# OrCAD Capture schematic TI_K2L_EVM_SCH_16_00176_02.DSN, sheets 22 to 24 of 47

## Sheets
22 PAGE25 : K2L_GPS AND USIM: size C; title: USIM, SOC UART 1.8v switching, 1.8v/3.3v GPIO INT, SOC UART, GPS
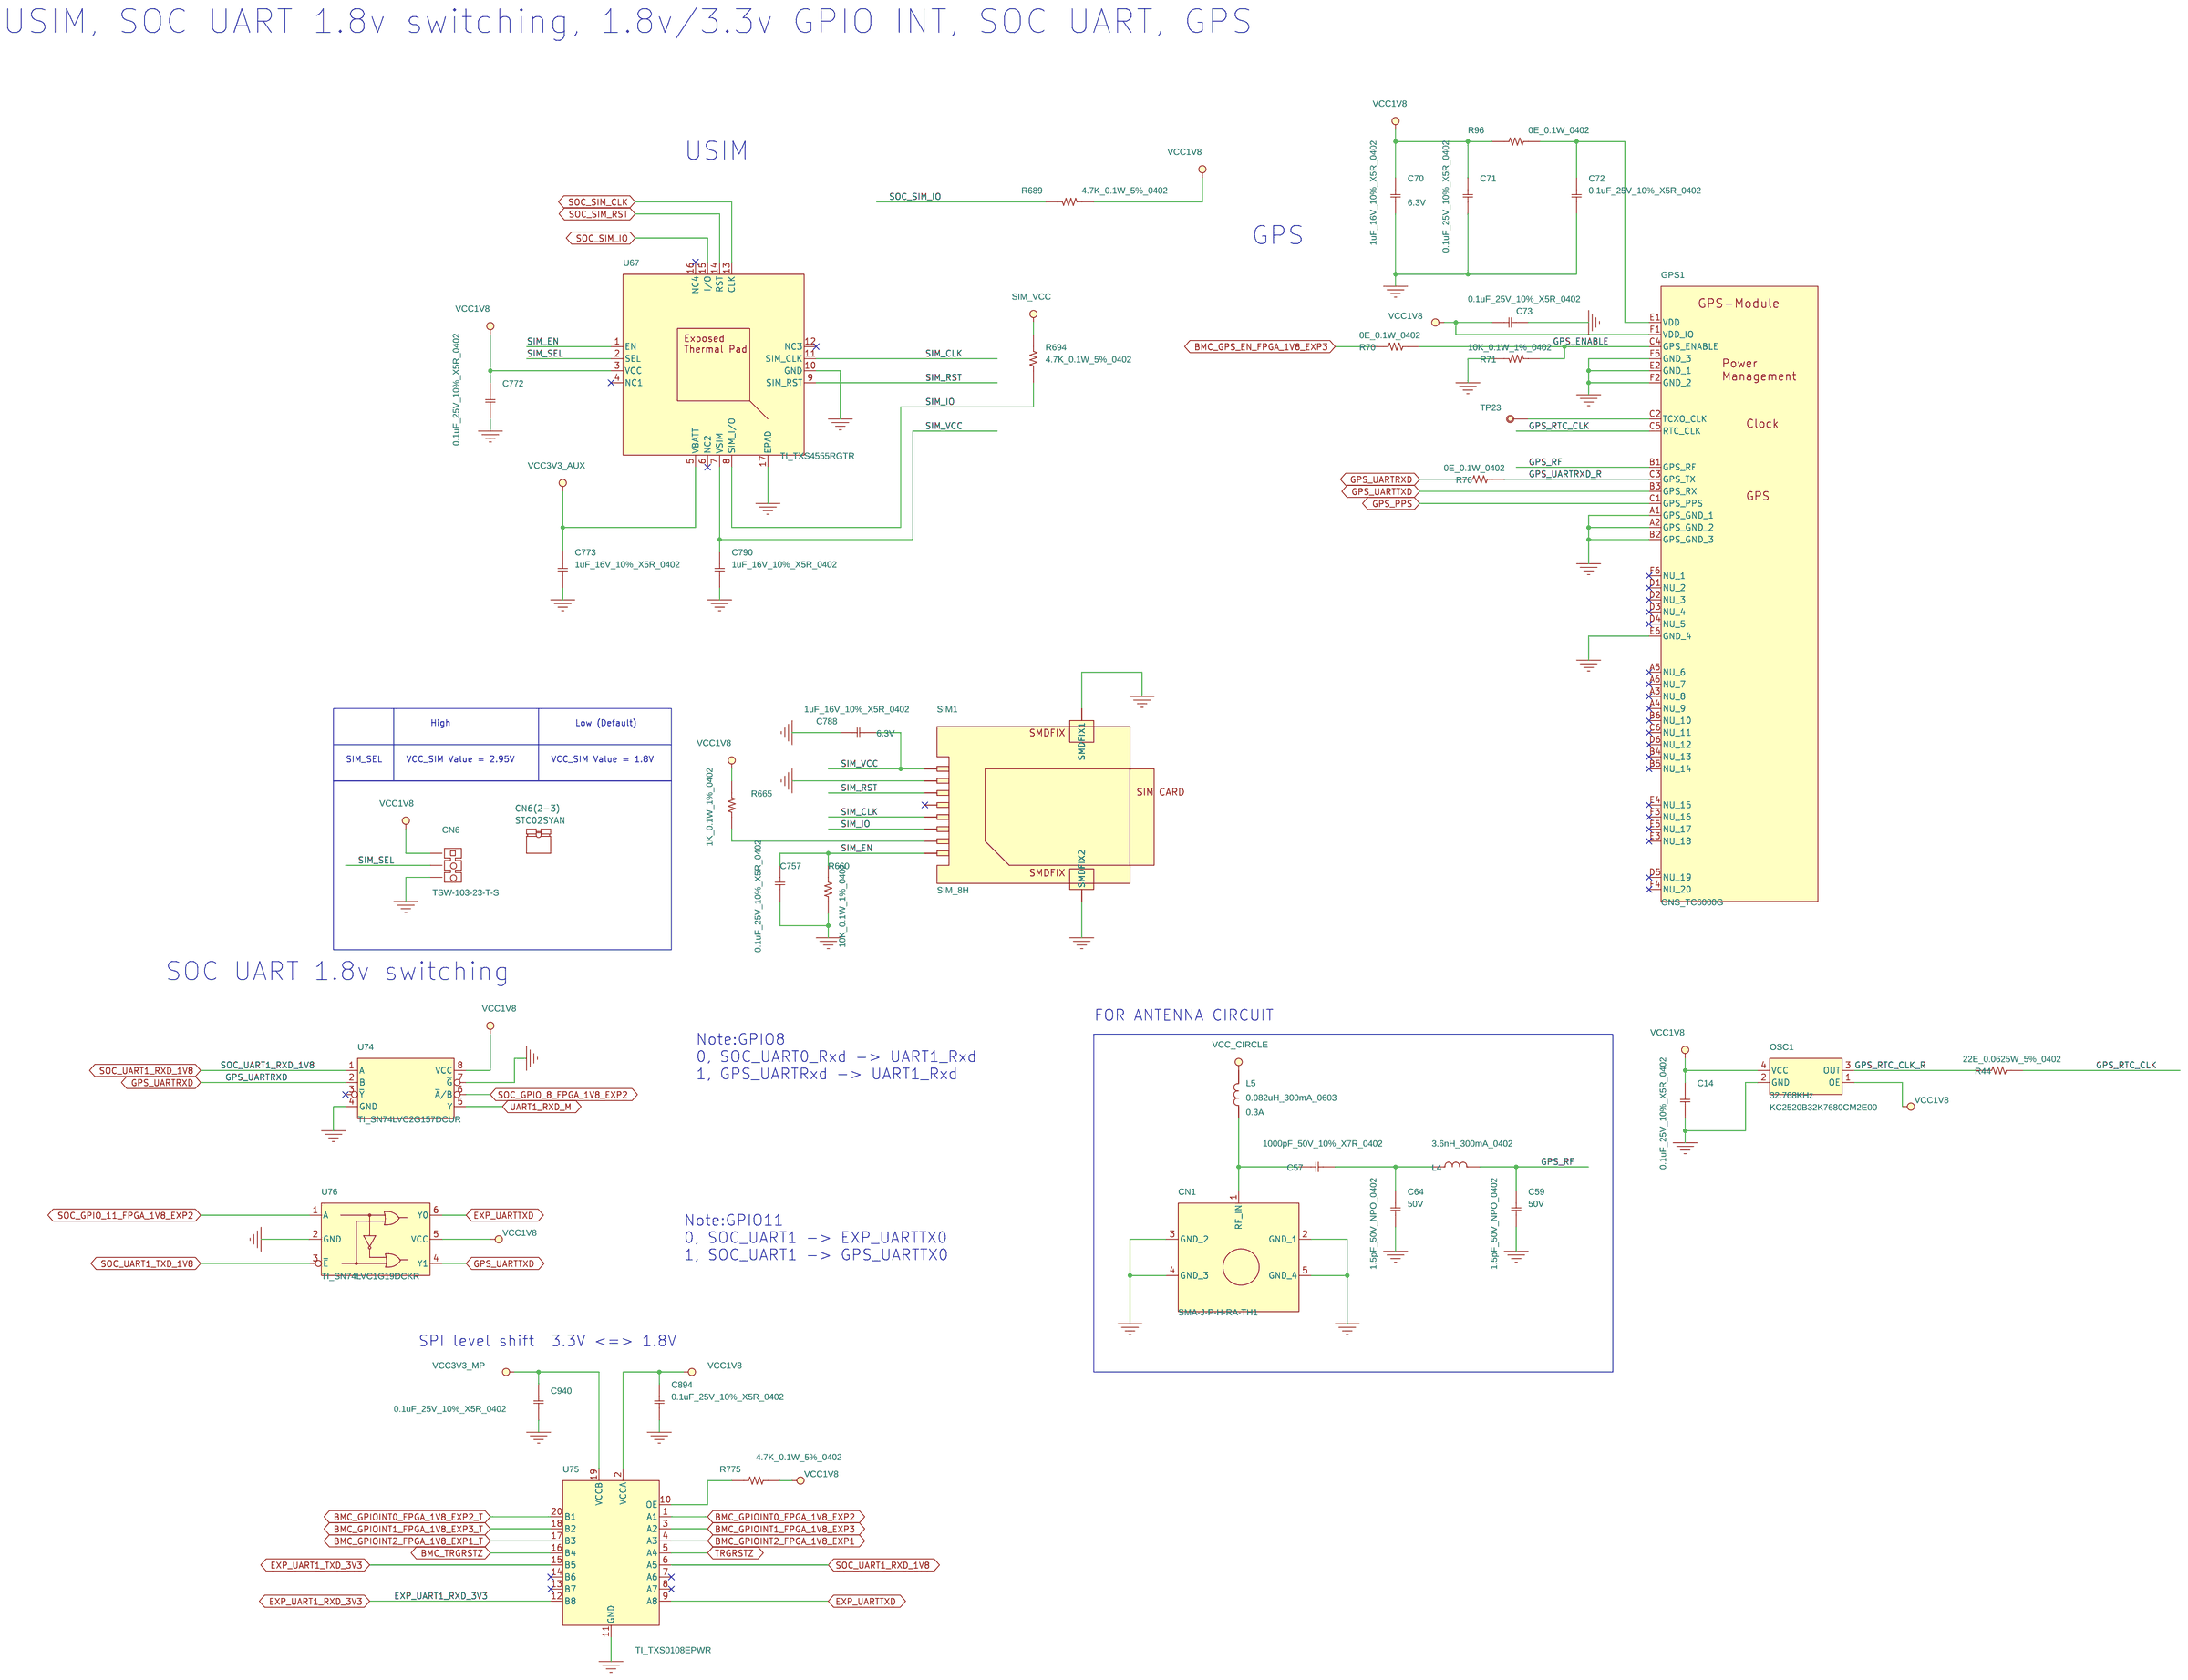
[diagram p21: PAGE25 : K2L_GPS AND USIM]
23 PAGE06 : POWER SEQUENCE_C: title: POWER SEQUENCE
24 PAGE40 : K2L_XDS200_POWER: size C; title: XDS200 Power
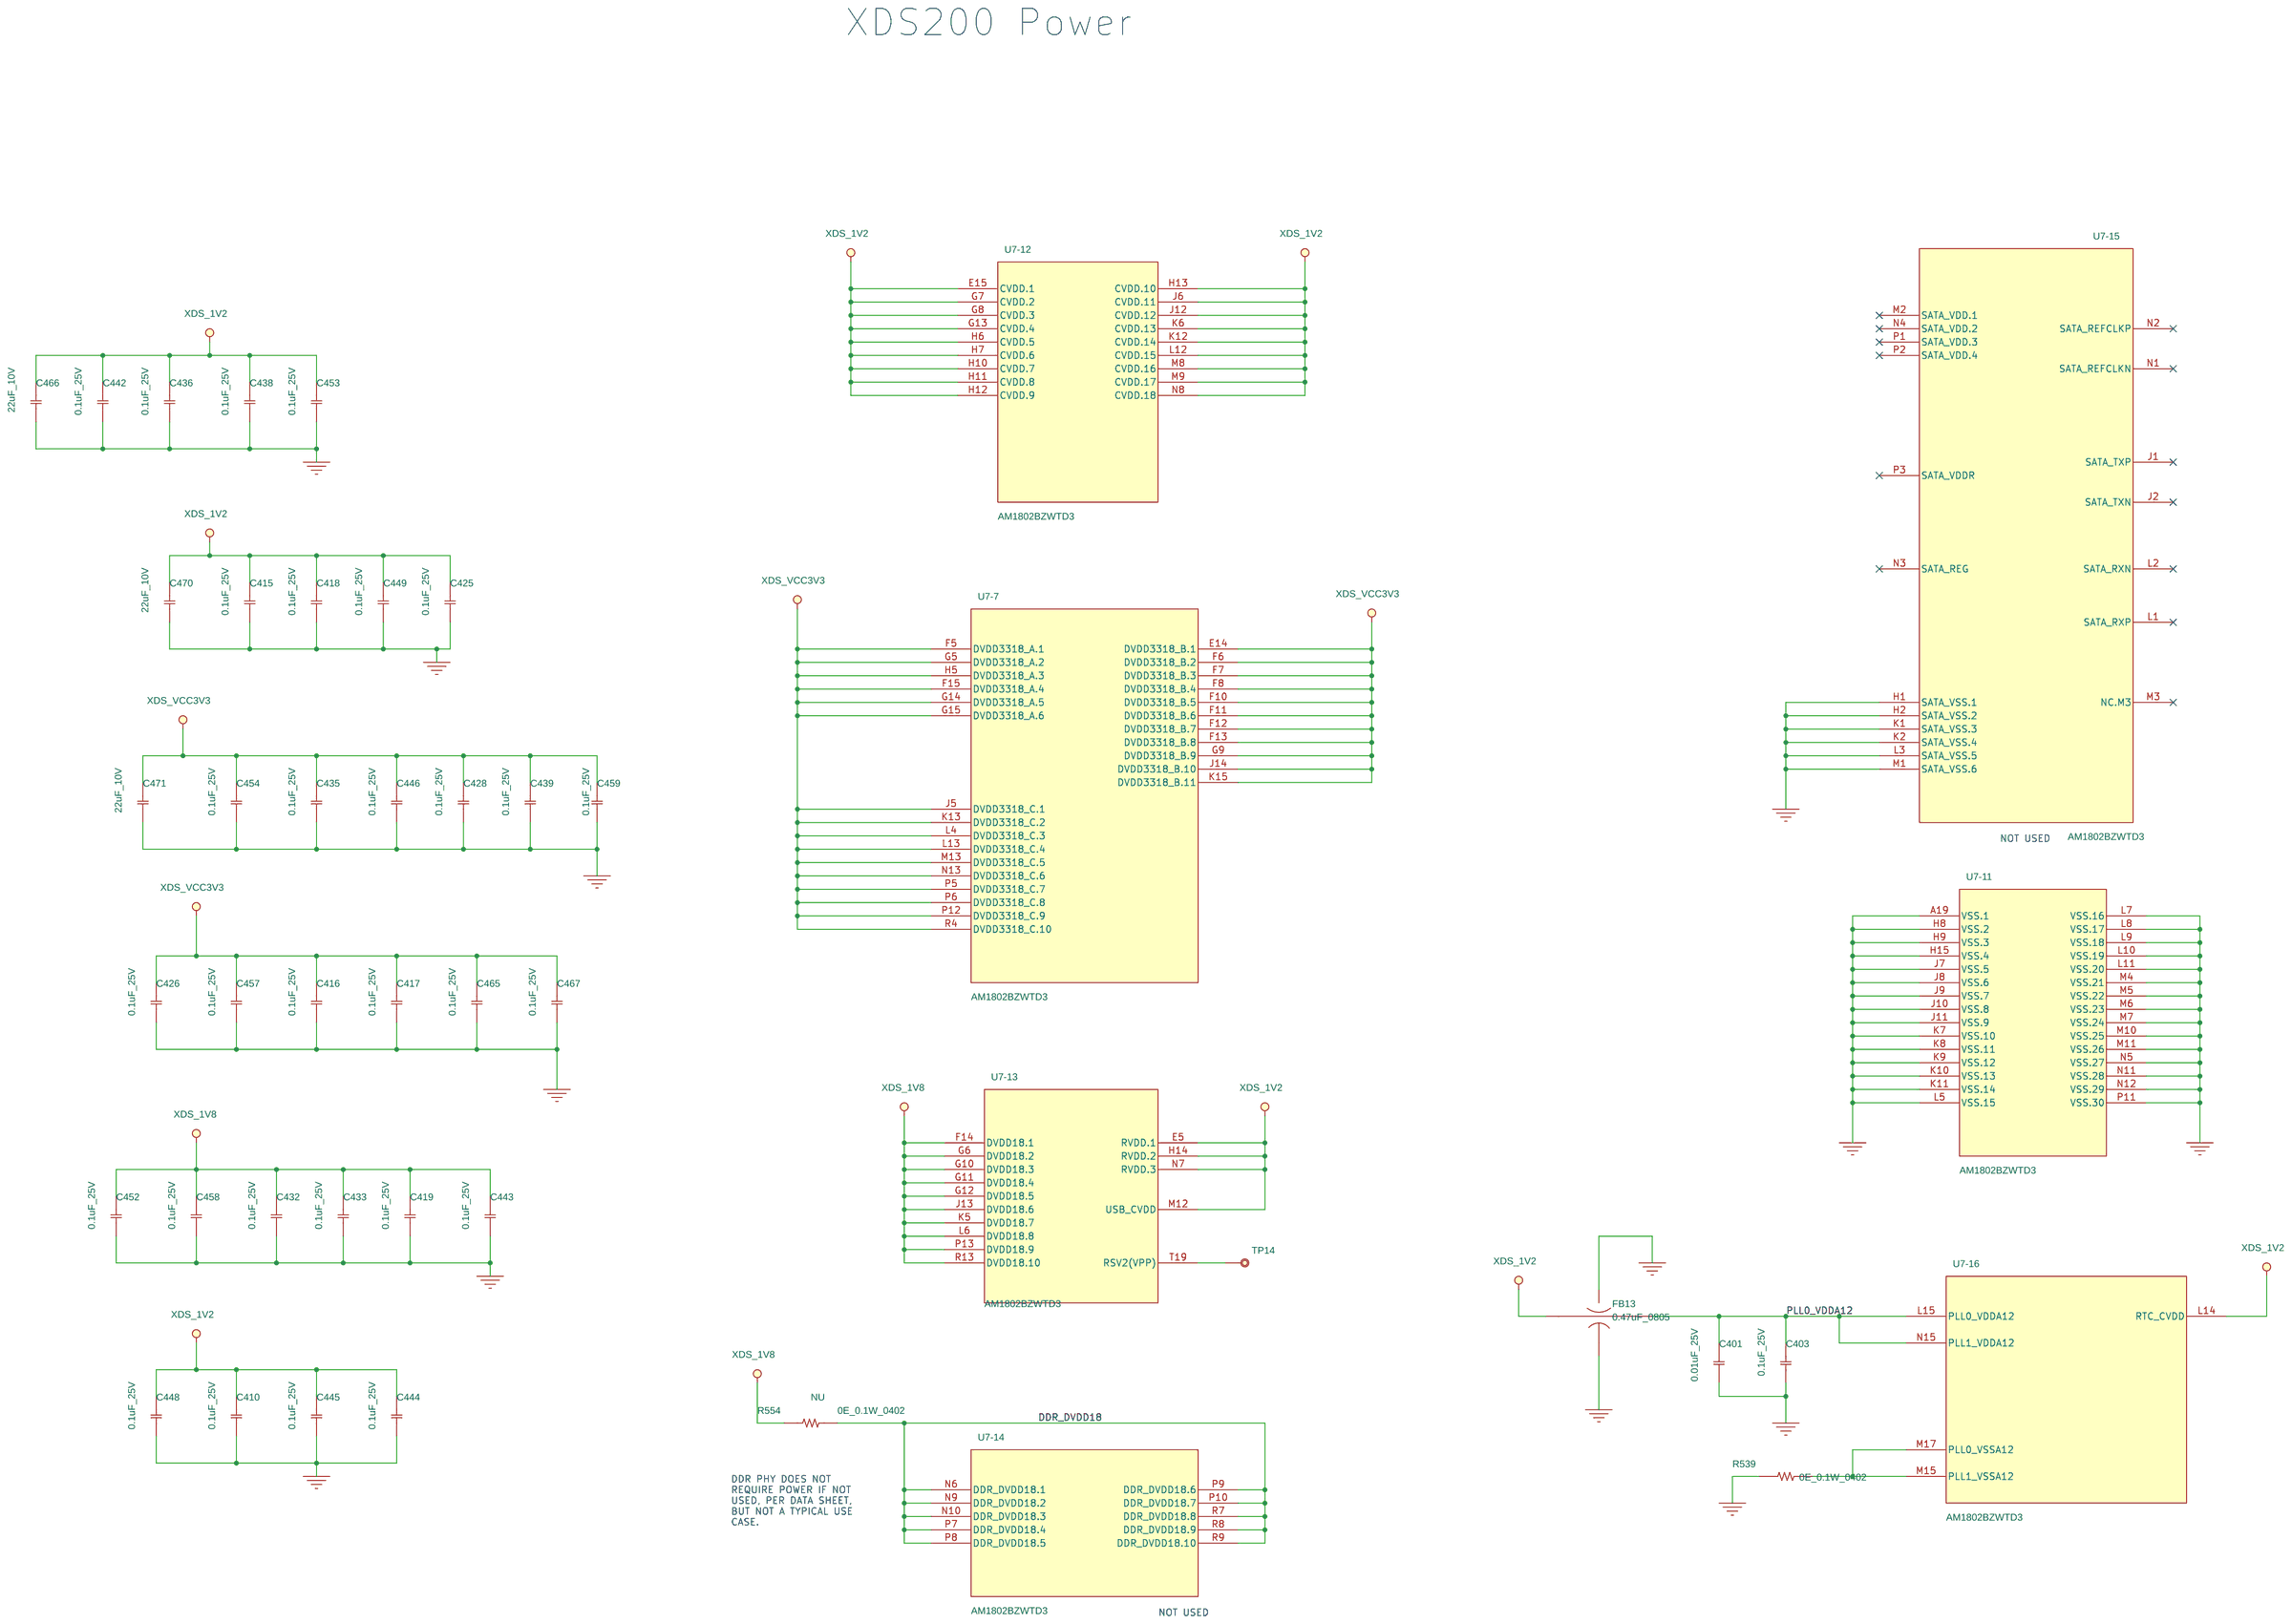
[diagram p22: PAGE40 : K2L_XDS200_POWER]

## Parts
sheet PAGE25 : K2L_GPS AND USIM
C14  0.1uF_25V_10%_X5R_0402  [C0402]
C57  1000pF_50V_10%_X7R_0402  [C0402]
C59  1.5pF_50V_NPO_0402  [C0402]
C64  1.5pF_50V_NPO_0402  [C0402]
C70  1uF_16V_10%_X5R_0402  [C0402]
C71  0.1uF_25V_10%_X5R_0402  [C0402]
C72  0.1uF_25V_10%_X5R_0402  [C0402]
C73  0.1uF_25V_10%_X5R_0402  [C0402]
C757  0.1uF_25V_10%_X5R_0402  [C0402]
C772  0.1uF_25V_10%_X5R_0402  [C0402]
C773  1uF_16V_10%_X5R_0402  [C0402]
C788  1uF_16V_10%_X5R_0402  [C0402]
C790  1uF_16V_10%_X5R_0402  [C0402]
C894  0.1uF_25V_10%_X5R_0402  [C0402]
C940  0.1uF_25V_10%_X5R_0402  [C0402]
CN1  SMA-J-P-H-RA-TH1  [SAMSMA-J-P-H-RA-TH1]
CN6  TSW-103-23-T-S  [BERG_1X3]
CN6(2-3)  STC02SYAN  [NA]
GPS1  GNS_TC6000G  [BGA_36P_60_394x366]
L4  3.6nH_300mA_0402  [L0402]
L5  0.082uH_300mA_0603  [INDC1608X95N]
OSC1  32.768KHz  [OSCCC200X250X70-4N]
R44  22E_0.0625W_5%_0402  [R0402]
R70  0E_0.1W_0402  [R0402]
R71  10K_0.1W_1%_0402  [R0402]
R76  0E_0.1W_0402  [R0402]
R96  0E_0.1W_0402  [R0402]
R660  10K_0.1W_1%_0402  [R0402]
R665  1K_0.1W_1%_0402  [R0402]
R689  4.7K_0.1W_5%_0402  [R0402]
R694  4.7K_0.1W_5%_0402  [R0402]
R775  4.7K_0.1W_5%_0402  [R0402]
SIM1  SIM_8H  [SIM_8P_FMS006Z-2001-1]
TP23  TP  [TP-S40]
U67  TI_TXS4555RGTR  [QFN_16P_20_118x118_TP59]
U74  TI_SN74LVC2G157DCUR  [SOIC_8P_20_79X122]
U75  TI_TXS0108EPWR  [SOIC_20P_26_256x252]
U76  TI_SN74LVC1G19DCKR  [SC-70_6P]
sheet PAGE39 : K2L_XDS200_3
U7  AM1802BZWTD3  [BGA80P_16X16_361]  (sections -1,-10,-11,-12,-13,-14,-15,-16,-2,-3,-4,-5,-6,-7,-8,-9)
sheet PAGE40 : K2L_XDS200_POWER
C401  0.01uF_25V  [C0402]
C403  0.1uF_25V  [C0402]
C410  0.1uF_25V  [C0402]
C415  0.1uF_25V  [C0402]
C416  0.1uF_25V  [C0402]
C417  0.1uF_25V  [C0402]
C418  0.1uF_25V  [C0402]
C419  0.1uF_25V  [C0402]
C425  0.1uF_25V  [C0402]
C426  0.1uF_25V  [C0402]
C428  0.1uF_25V  [C0402]
C432  0.1uF_25V  [C0402]
C433  0.1uF_25V  [C0402]
C435  0.1uF_25V  [C0402]
C436  0.1uF_25V  [C0402]
C438  0.1uF_25V  [C0402]
C439  0.1uF_25V  [C0402]
C442  0.1uF_25V  [C0402]
C443  0.1uF_25V  [C0402]
C444  0.1uF_25V  [C0402]
C445  0.1uF_25V  [C0402]
C446  0.1uF_25V  [C0402]
C448  0.1uF_25V  [C0402]
C449  0.1uF_25V  [C0402]
C452  0.1uF_25V  [C0402]
C453  0.1uF_25V  [C0402]
C454  0.1uF_25V  [C0402]
C457  0.1uF_25V  [C0402]
C458  0.1uF_25V  [C0402]
C459  0.1uF_25V  [C0402]
C465  0.1uF_25V  [C0402]
C466  22uF_10V  [C0805]
C467  0.1uF_25V  [C0402]
C470  22uF_10V  [C0805]
C471  22uF_10V  [C0805]
FB13  0.47uF_0805  [FIL_NFM21PC]
R539  0E_0.1W_0402  [R0402]
R554  0E_0.1W_0402  [R0402]
TP14  TP  [TP-S40]

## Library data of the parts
C14 C71-C73 C757 C772 C894 C940 = 11_C_0: CAP CER 0.1UF 25V 10% X5R 0402; Avalue_Part_Number: E1123510400H; Distributor_name: DIGIKEY; Distributor_part_number: 445-4964-1-ND; EIC Part#: 03_00470_02; MOUNTED: <MOUNTED>; Manufacture: TDK Corporation; Manufacture Part Number: C1005X5R1E104K050BC; Manufacture(English): TDK Corporation; Manufacture_Part_Number: GRM155R71C104KA88D; Manufacturer: TDK Corporation; Manufacturer_Part_No: C1005X5R1E104K050BC; Mfg: Murata Electronics North America; Mfg Part#: 03_00470_02; Mfr_name: TDK Corporation; Mfr_part_number: C1005X5R1E104K050BC; Package: 0402; Price @ 1: 0.10000; Price @ 1K: 0.00420; ProcessType: SMT; Tolerance: 10%; Vendor: DIGIKEY; Vendor Part#: 445-4964-1-ND; Vendor_Part_No: 445-4964-1-ND; eI Part#: 03_00470_02
C57 = 11_C_0: CAP CER 1000PF 50V 10% X7R 0402; Advansus_Part_Number: 11G232110214030; Characteristic: 50V; Distributor_name: DIGIKEY; Distributor_part_number: 1276-1493-1-ND; EIC Part#: 03_00591_01; Manufacture: Samsung; Manufacture Part Number: CL05B102KB5NFNC; Manufacture(English): Samsung; Manufacture_Part_Number: CL05B102KB5NFNC; Manufacturer: Samsung; Manufacturer_Part_No: CL05B102KB5NFNC; Mfg: Samsung; Mfg Part#: CL05B102KB5NFNC; Mfr_name: Samsung; Mfr_part_number: CL05B102KB5NFNC; Package: 0402; Part_Number: 1124510291; Price @ 1: 0.10000; Price @ 10K: 0.00216; Price @ 1K: 0.00309; ProcessType: SMT; Tolerance: 10%; Vendor: DIGIKEY; Vendor Part#: 1276-1493-1-ND; Vendor_Part_No: 1276-1493-1-ND; eI Part#: 03_00591_01
C59 C64 = 11_C_0: CAP CER 1.5PF 50V NPO 0402; Avalue_Part_Number: E1127815A00H; Characteristic: 50V; Distributor_name: DIGIKEY; Distributor_part_number: 490-4916-1-ND; EIC Part#: 03_00419_01; Manufacture: Murata; Manufacture Part Number: GCM1555C1H1R5CZ13D; Manufacture(English): Murata; Manufacture_Part_Number: GCM1555C1H1R5CZ13D; Manufacturer: Murata; Manufacturer_Part_No: GCM1555C1H1R5CZ13D; Mfg: Murata Electronics North America; Mfg Part#: 03_00419_01; Mfr_name: Murata; Mfr_part_number: GCM1555C1H1R5CZ13D; Package: 0402; Part_Number: 1100001410; Price @ 1: 0.11000; Price @ 10K: 0.01428; Price @ 1K: 0.02040; ProcessType: SMT; Tolerance: 0.25pF; Vendor: DIGIKEY; Vendor_Part_No: 490-4916-1-ND; eI Part#: 03_00419_01
C70 C773 C788 C790 = 11_C_0: CAP CER 1UF 16V 10% X5R 0402; Characteristic: 6.3V; Distributor_name: DIGIKEY; Distributor_part_number: 445-4978-1-ND; EIC Part#: 03_00355_04; Manufacture: TDK Corporation; Manufacture Part Number: C1005X5R1C105K050BC; Manufacture(English): TDK Corporation; Manufacture_Part_Number: C1005X5R1C105K050BC; Manufacturer: TDK Corporation; Manufacturer_Part_No: C1005X5R1C105K050BC; Mfg: TDK Corporation; Mfg Part#: C1005X5R1C105K050BC; Mfr_name: TDK Corporation; Mfr_part_number: C1005X5R1C105K050BC; Package: 0402; Part_Number: 1100000870; Price @ 1: 0.10000; Price @ 10K: 0.01155; Price @ 1K: 0.01650; ProcessType: SMT; Tolerance: 10%; Vendor: DIGIKEY; Vendor_Part_No: 445-4978-1-ND; eI Part#: 03_00355_04
CN1 = 1654_RF-SMAC037_0: RF CONN 50E SMA-J-P-H-RA-TH1; Distributor_name: TBD; Distributor_part_number: TBD; EIC Part#: TBD; Manufacture: Samtec Inc; Manufacture(English): Samtec Inc; Manufacturer: Samtec Inc; Mfg: Samtec Inc; Mfg Part#: TBD; Mfr_name: Samtec Inc; Package: SMA5P; Part_Number: 1654001599; Price @ 1: TBD; Price @ 10K: TBD; Price @ 1K: TBD; ProcessType: DIP; Vendor: TBD; Vendor_Part_No: TBD; eI Part#: 09_00596_01
CN6 = 1653_JH3X1V-51462803_0: CONN HEADER 3POS .100 SNGL TIN; Advansus_Part_Number: 12GA1653000850; Distributor_name: DIGIKEY; Distributor_part_number: SAM1075-03-ND; EIC Part#: 09_00962_01; Manufacture: Samtec Inc; Manufacture(English): Samtec Inc; Manufacturer: Samtec Inc; Mfg: Samtec; Mfg Part#: 09_00190_01; Mfr_name: Samtec Inc; Package: PH3x1P-2.54; Part_Number: 1653000850; Price @ 1: 0.53000; Price @ 10K: 0.23098; Price @ 1K: 0.26331; ProcessType: DIP; Vendor: DIGIKEY; Vendor_Part_No: SAM1075-03-ND; eI Part#: 09_00962_01
CN6(2-3) = 1653_MINIJUMPER22.54MM_0: CONN JUMPER SHORTING TIN; Advansus_Part_Number: 12GA1653300100; Distributor_name: DIGIKEY; Distributor_part_number: S9000-ND; EIC Part#: 09_00190_01; Manufacture: Sullins Connector; Manufacture(English): Sullins Connector; Manufacturer: Sullins Connector; Mfg: Sullins Connector Solutions; Mfg Part#: 09_00190_01; Mfr_name: Sullins Connector; Package: MINIJUMPER2P-2.54; Part_Number: 1653300100; Price @ 1: 0.29000; Price @ 10K: 0.04800; Price @ 1K: 0.06080; ProcessType: Others; Vendor: DIGIKEY; Vendor_Part_No: S9000-ND; eI Part#: 09_00190_01
GPS1 = 141_GNS_TC6000G_1: IC TC6000G GPS SMD BGA 36P GNS-GmbH; AVL_Part: Non-AVL; Distributor_name: TBD; Distributor_part_number: TBD; EIC Part#: TBD; Manufacture: GNS; Manufacture Part Number: TC6000G; Manufacture(English): GNS; Manufacture_Part_Number: TC6000G; Manufacturer: GNS; Manufacturer_Part_No: TC6000G; Mfg: GNS; Mfg Part#: TBD; Mfr_name: GNS; Mfr_part_number: TC6000G; Package: BGA36; Part_Number: 1410021620; Price @ 1: TBD; Price @ 10K: TBD; Price @ 1K: TBD; ProcessType: SMT; Vendor: TBD; Vendor_Part_No: TBD; eI Part#: TBD
L4 = 1211_L_0: INDUCTOR 3.6NH 300MA 0402; Characteristic: 0.3A; Distributor_name: DIGIKEY; Distributor_part_number: 490-6562-1-ND; EIC Part#: TBD; Manufacture: Murata; Manufacture Part Number: LQG15HN3N6S02D; Manufacture(English): Murata; Manufacture_Part_Number: LQG15HN3N6S02D; Manufacturer: Murata; Manufacturer_Part_No: LQG15HN3N6S02D; Mfg: Murata; Mfg Part#: LQG15HN3N6S02D; Mfr_name: Murata; Mfr_part_number: LQG15HN3N6S02D; Package: 0402; Part_Number: 1211004306; Price @ 1: 0.10000; Price @ 10K: 0.01872; Price @ 1K: 0.03042; ProcessType: SMT; Vendor: DIGIKEY; Vendor_Part_No: 490-6562-1-ND; eI Part#: TBD
L5 = 1211_L_0: INDUCTOR 82NH 300MA 0603; Advansus_Part_Number: 09G023821009; Characteristic: 0.3A; Distributor_name: DIGIKEY; Distributor_part_number: 490-6585-1-ND; EIC Part#: TBD; Manufacture: Murata; Manufacture Part Number: LQG18HN82NJ00D; Manufacture(English): Murata; Manufacture_Part_Number: LQG18HN82NJ00D; Manufacturer: Murata; Manufacturer_Part_No: LQG18HN82NJ00D; Mfg: Murata; Mfg Part#: TBD; Mfr_name: Murata; Mfr_part_number: LQG18HN82NJ00D; Package: 0603; Part_Number: 1211002838; Price @ 1: 0.26000; Price @ 10K: 0.08640; Price @ 1K: 0.12480; ProcessType: SMT; Tolerance: 5%; Vendor: DIGIKEY; Vendor_Part_No: 490-6585-1-ND; eI Part#: TBD
OSC1 = 1233_OSC_4P_0: OSCILLATOR 32.768KHZ 3.3V SMD; Characteristic: KC2520B32K7680CM2E00; Distributor_name: DIGIKEY; Distributor_part_number: 1253-1026-1-ND; EIC Part#: 08_00173_01; Manufacture: AVX Corp/Kyocera Corp; Manufacture Part Number: KC2520B32K7680CM2E00; Manufacture(English): AVX Corp/Kyocera Corp; Manufacture_Part_Number: KC2520B32K7680CM2E00; Manufacturer: AVX Corp/Kyocera Corp; Manufacturer_Part_No: KC2520B32K7680CM2E00; Mfg: AVX Corp/Kyocera Corp; Mfg Part#: 08_00173_01; Mfr_name: AVX Corp/Kyocera Corp; Mfr_part_number: KC2520B32K7680CM2E00; Oper. Temp. Range: -40C to 85C; Package: OSC7*5mm; Part_Number: KC2520B32K7680CM2E00; Price @ 1: 3.00000; Price @ 10K: 1.12000; Price @ 1K: 1.20000; ProcessType: SMT; Vendor: DIGIKEY; Vendor Part#: 1253-1026-2-ND; Vendor_Part_No: 1253-1026-1-ND; eI Part#: 08_00173_01
R44 = 10_R_0: RES 22 OHM 1/16W 1% 0402 SMD; Characteristic: 5%; Distributor_name: DIGIKEY; Distributor_part_number: P22JCT-ND; EIC Part#: 02_00233_01; MOUNTED: <MOUNTED>; Manufacture: Panasonic - ECG; Manufacture Part Number: ERJ-2GEJ220X; Manufacture(English): Panasonic - ECG; Manufacture_Part_Number: ERJ-2GEJ220X; Manufacturer: Panasonic - ECG; Manufacturer_Part_No: ERJ-2GEJ220X; Mfg: Panasonic - ECG; Mfg Part#: ERJ-2GEJ220X; Mfr_name: Panasonic - ECG; Mfr_part_number: ERJ-2GEJ220X; Package: 0402; Part_Number: 105A722064; Price @ 1: 0.10000; Price @ 10K: 0.00132; Price @ 1K: 0.00233; ProcessType: SMT; Tolerance: 5%; Vendor: DIGIKEY; Vendor Part#: P22JCT-ND; Vendor_Part_No: P22JCT-ND; eI Part#: 02_00233_01
R70 R76 R96 = 10_R_0: RES 0.0 OHM 1/10W JUMP 0402 SMD; Characteristic: 5%; Distributor_name: DIGIKEY; Distributor_part_number: P0.0JCT-ND; EIC Part#: 02_00019_01; Manufacture: Panasonic - ECG; Manufacture Part Number: ERJ-2GE0R00X; Manufacture(English): Panasonic - ECG; Manufacture_Part_Number: ERJ-2GE0R00X; Manufacturer: Panasonic - ECG; Manufacturer_Part_No: ERJ-2GE0R00X; Mfg: Panasonic Electronic Components; Mfg Part#: 02_00019_01; Mfr_name: Panasonic - ECG; Mfr_part_number: ERJ-2GE0R00X; Package: 0402; Part_Number: 105A700004; Price @ 1: 0.05000; Price @ 10K: 0.00248; Price @ 1K: 0.00480; ProcessType: SMT; Tolerance: 5%; Vendor: DIGIKEY; Vendor_Part_No: P0.0JCT-ND; eI Part#: 02_00019_01
R71 = 10_R_0: RES 10K OHM 1/10W 1% 0402 SMD; Characteristic: 1%; Distributor_name: DIGIKEY; Distributor_part_number: P10.0KLCT-ND; EIC Part#: 02_00027_01; Manufacture: Panasonic - ECG; Manufacture Part Number: ERJ-2RKF1002X; Manufacture(English): Panasonic - ECG; Manufacture_Part_Number: ERJ-2RKF1002X; Manufacturer: Panasonic - ECG; Manufacturer_Part_No: ERJ-2RKF1002X; Mfg: PANASONIC ELECTRONIC COMPONENTS (VA); Mfg Part#: 02_00027_01; Mfr_name: Panasonic - ECG; Mfr_part_number: ERJ-2RKF1002X; Package: 0402; Part_Number: 105A50103A; Price @ 1: 0.10000; Price @ 10K: 0.00347; Price @ 1K: 0.00672; ProcessType: SMT; Tolerance: 1%; Vendor: DIGIKEY; Vendor_Part_No: P10.0KLCT-ND; eI Part#: 02_00027_01
R660 = 10_R_0: RES 10K OHM 1/10W 1% 0402 SMD; Characteristic: 1%; Distributor_name: DIGIKEY; Distributor_part_number: P10.0KLCT-ND; EIC Part#: 02_00027_01; MOUNTED: <MOUNTED>; Manufacture: Panasonic - ECG; Manufacture Part Number: ERJ-2RKF1002X; Manufacture(English): Panasonic - ECG; Manufacture_Part_Number: ERJ-2RKF1002X; Manufacturer: Panasonic - ECG; Manufacturer_Part_No: ERJ-2RKF1002X; Mfg: PANASONIC ELECTRONIC COMPONENTS (VA); Mfg Part#: 02_00027_01; Mfr_name: Panasonic - ECG; Mfr_part_number: ERJ-2RKF1002X; Package: 0402; Part_Number: 105A50103A; Price @ 1: 0.10000; Price @ 10K: 0.00347; Price @ 1K: 0.00672; ProcessType: SMT; Tolerance: 1%; Vendor: DIGIKEY; Vendor_Part_No: P10.0KLCT-ND; eI Part#: 02_00027_01
R665 = 10_R_0: RES 1.00K OHM 1/10W 1% 0402 SMD; Characteristic: 1%; Distributor_name: DIGIKEY; Distributor_part_number: P1.00KLCT-ND; EIC Part#: 02_00045_01; MOUNTED: <MOUNTED>; Manufacture: Panasonic - ECG; Manufacture Part Number: ERJ-2RKF1001X; Manufacture(English): Panasonic - ECG; Manufacture_Part_Number: ERJ-2RKF1001X; Manufacturer: Panasonic - ECG; Manufacturer_Part_No: ERJ-2RKF1001X; Mfg: Panasonic Electronic Components; Mfg Part#: 02_00045_01; Mfr_name: Panasonic - ECG; Mfr_part_number: ERJ-2RKF1001X; Package: 0402; Part_Number: 105A510014; Price @ 1: 0.10000; Price @ 10K: 0.00347; Price @ 1K: 0.00672; ProcessType: SMT; Tolerance: 1%; Vendor: DIGIKEY; Vendor_Part_No: P1.00KLCT-ND; eI Part#: 02_00045_01
R689 R694 R775 = 10_R_0: RES 4.7K OHM 1/10W 5% 0402 SMD; Advansus_Part_Number: 10G212472004030; Avalue_Part_Number: E1050704720H; Characteristic: 5%; Distributor_name: DIGIKEY; Distributor_part_number: P4.7KJCT-ND; EIC Part#: 02_00023_01; MOUNTED: <MOUNTED>; Manufacture: Panasonic - ECG; Manufacture Part Number: ERJ-2GEJ472X; Manufacture(English): Panasonic - ECG; Manufacture_Part_Number: ERJ-2GEJ472X; Manufacturer: Panasonic - ECG; Manufacturer_Part_No: ERJ-2GEJ472X; Mfg: Panasonic Electronic Components; Mfg Part#: 02_00266_01; Mfr_name: Panasonic - ECG; Mfr_part_number: ERJ-2GEJ472X; Package: 0402; Part_Number: 105A747014; Price @ 1: 0.10000; Price @ 10K: 0.00347; Price @ 1K: 0.00672; ProcessType: SMT; Tolerance: 5%; Vendor: DIGIKEY; Vendor_Part_No: P4.7KJCT-ND; eI Part#: 02_00023_01
SIM1 = 1654_SIMCARD_8P_FMS006Z-2001_0: SIM card conn. 8P 1.27mm 90D(F) SMD FMS006Z-2001; AVL_Part: Non-AVL; Distributor_name: ELEMENT14; Distributor_part_number: 1143956; EIC Part#: TBD; Manufacture: Yamaichi Electronics; Manufacture Part Number: FMS006Z-2001-1; Manufacture(English): Yamaichi Electronics; Manufacture_Part_Number: FMS006Z-2001-1; Manufacturer: Yamaichi Electronics; Manufacturer_Part_No: FMS006Z-2001-1; Mfg: Yamaichi Electronics; Mfg Part#: TBD; Mfr_name: Yamaichi Electronics; Mfr_part_number: FMS006Z-2001-1; Package: SIM8P; Part_Number: 1654010024; Price @ 1: 8.92700; Price @ 10K: 4.56500; Price @ 1K: 4.56500; ProcessType: SMT; Vendor: ELEMENT14; Vendor_Part_No: 1143956; eI Part#: NA
TP23 = 00_TP28_0: TEST PAD TP; Advansus_Part_Number: 0030000003; Avalue_Part_Number: 0030000003; Distributor_name: NA; Distributor_part_number: NA; EIC Part#: NA; Manufacture: NA; Manufacture Part Number: NA; Manufacture(English): NA; Manufacture_Part_Number: NA; Manufacturer: NA; Manufacturer_Part_No: NA; Mfg: NA; Mfg Part#: NA; Mfr_name: NA; Mfr_part_number: NA; Part_Number: 0030000003; Price @ 1: NA; Price @ 10K: NA; Price @ 1K: NA; ProcessType: SMT; Vendor: NA; Vendor_Part_No: NA; eI Part#: NA
U67 = 141_TI_TXS4555RGTR_1: IC V-LEVEL XLATR SIM CARD 16QFN; Distributor_name: DIGIKEY; Distributor_part_number: 296-28382-1-ND; EIC Part#: TBD; Manufacture: TI; Manufacture Part Number: TXS4555RGTR; Manufacture(English): TI; Manufacture_Part_Number: TXS4555RGTR; Manufacturer: TI; Manufacturer_Part_No: TXS4555RGTR; Mfg: TI; Mfg Part#: TBD; Mfr_name: TI; Mfr_part_number: TXS4555RGTR; Package: QFN16; Part_Number: 1410021605; Price @ 1: 1.91000; Price @ 10K: 0.81000; Price @ 1K: 0.89400; ProcessType: SMT; Vendor: DIGIKEY; Vendor_Part_No: 296-28382-1-ND; eI Part#: TBD
U74 = 141_TI_SN74LVC2G157_0: IC MULTIPLEXER DATA SEL US8; Distributor_name: DIGIKEY; Distributor_part_number: 296-12605-1-ND; EIC Part#: 01_01117_01; Manufacture: TI; Manufacture Part Number: SN74LVC2G157DCUR; Manufacture(English): TI; Manufacture_Part_Number: SN74LVC2G157DCUR; Manufacturer: TI; Manufacturer_Part_No: SN74LVC2G157DCUR; Mfg: TI; Mfg Part#: 01_01117_01; Mfr_name: TI; Mfr_part_number: SN74LVC2G157DCUR; Package: VSSOP8; Part_Number: 1410023116-01; Price @ 1: 0.70000; Price @ 10K: 0.24650; Price @ 1K: 0.28050; ProcessType: SMT; Vendor: DIGIKEY; Vendor_Part_No: 296-12605-1-ND; eI Part#: 01_01135_01
U75 = 141_TI_TXS0108EPWR_0: IC 8BIT NON-INV TRANSLTR 20TSSOP; Distributor_name: DIGIKEY; Distributor_part_number: 296-23011-1-ND; EIC Part#: 01_00472_01; Manufacture: TI; Manufacture Part Number: TXS0108EPWR; Manufacture(English): TI; Manufacture_Part_Number: TXS0108EPWR; Manufacturer: TI; Manufacturer_Part_No: TXS0108EPWR; Mfg: TI; Mfg Part#: 01_00472_01; Mfr_name: TI; Mfr_part_number: TXS0108EPWR; Package: TSSOP20; Part_Number: 1410020326; Price @ 1: 2.30000; Price @ 10K: 0.90000; Price @ 1K: 0.91800; ProcessType: SMT; Vendor: DIGIKEY; Vendor_Part_No: 296-23011-1-ND; eI Part#: 01_01146_01
U76 = 141_TI_SN74LVC1G19DCKR_0: IC MUX DECODER SNGL 1OF2 SC70-6; AVL_Part: AVL; Distributor_name: DIGIKEY; Distributor_part_number: 296-17991-1-ND; EIC Part#: TBD; Manufacture: TI; Manufacture Part Number: SN74LVC1G19DCKR; Manufacture(English): TI; Manufacture_Part_Number: SN74LVC1G19DCKR; Manufacturer: TI; Manufacturer_Part_No: SN74LVC1G19DCKR; Mfg: TI; Mfg Part#: TBD; Mfr_name: TI; Mfr_part_number: SN74LVC1G19DCKR; Package: SC70-6; Part_Number: 1410019373; Price @ 1: 0.40000; Price @ 10K: 0.09900; Price @ 1K: 0.11100; ProcessType: SMT; Vendor: DIGIKEY; Vendor_Part_No: 296-17991-1-ND; eI Part#: 01_00570_01
U7 = OMAP-L138_new_5: IC ARM9 CORTEX MPU 361NFBGA; Distributor_name: DIGIKEY; Distributor_part_number: AM1802BZWTD3-ND; EIC Part#: 01_01135_01; Manufacture: TI; Manufacture(English): TI; Manufacturer: TI; Mfg: TI; Mfg Part#: 01_01135_01; Mfr_name: TI; Part #: 103922-0001R; Price @ 1: 14.51000; Price @ 1K: 14.51000; Vendor: DIGIKEY; Vendor_Part_No: AM1802BZWTD3-ND; eI Part#: 01_01147_01
C401 = 11_C_0: CAP CER 10000PF 25V 10% X7R 0402; Alt Mfg: Murata; Alt Mfg Part#: GRM155R71C103KA01D; Distributor_name: DIGIKEY; Distributor_part_number: 445-1260-1-ND; EIC Part#: 03_00029_04; Manufacture: TDK Corporation; Manufacture Part Number: C1005X7R1E103K; Manufacture(English): TDK Corporation; Manufacture_Part_Number: C1005X7R1E103K; Manufacturer: TDK Corporation; Manufacturer_Part_No: C1005X7R1E103K; Mfg: TDK Corporation; Mfg Part#: 03_00029_04; Mfr_name: TDK Corporation; Mfr_part_number: C1005X7R1E103K; Oper. Temp. Range: -55C to 125C; Package: 0402; Price @ 1: 0.10000; Price @ 10K: 0.00420; Price @ 1K: 0.00600; ProcessType: SMT; RoHS: Yes; Tolerance: 10%; Vendor: DIGIKEY; Vendor Part#: PCC103BQCT-ND; Vendor_Part_No: 445-1260-1-ND; Voltage: 16V; eI Part#: 03_00029_04
C403 C410 C415-C419 C425 C426 C428 C432 C433 C435 C436 C438 C439 C442-C446 C448 C449 C452-C454 C457-C459 C465 C467 = 11_C_0: CAP CER 0.1UF 25V 10% X5R 0402; Alt Mfg: Taiyo Yuden; Distributor_name: DIGIKEY; Distributor_part_number: 445-4964-1-ND; EIC Part#: 03_00470_02; Manufacture: TDK Corporation; Manufacture Part Number: C1005X5R1E104K050BC; Manufacture(English): TDK Corporation; Manufacture_Part_Number: GRM155R61E104KA87D; Manufacturer: TDK Corporation; Manufacturer_Part_No: C1005X5R1E104K050BC; Mfg: Murata Electronics North America; Mfg Part#: 03_00470_02; Mfr_name: TDK Corporation; Mfr_part_number: C1005X5R1E104K050BC; Oper. Temp. Range: -55°C ~ 85°C; Package: 0402; Price @ 1: 0.10000; Price @ 1K: 0.00960; ProcessType: SMT; RoHS: Yes; Tolerance: 10%; Vendor: DIGIKEY; Vendor Part#: 445-4964-1-ND; Vendor_Part_No: 445-4964-1-ND; eI Part#: 03_00470_02
C466 C470 C471 = 11_C_0: CAP CER 22UF 10V 20% X5R 0805; Distributor_name: DIGIKEY; Distributor_part_number: 587-1958-1-ND; EIC Part#: 03_00263_01; Manufacture: Taiyo Yuden; Manufacture Part Number: LMK212BJ226MG-T; Manufacture(English): Taiyo Yuden; Manufacture_Part_Number: LMK212BJ226MG-T; Manufacturer: Taiyo Yuden; Manufacturer_Part_No: LMK212BJ226MG-T; Mfg: Taiyo Yuden; Mfg Part#: 03_00263_01; Mfr_name: Taiyo Yuden; Mfr_part_number: LMK212BJ226MG-T; Oper. Temp. Range: -55C to 85C; Package: 0805; Price @ 1: 0.53000; Price @ 10K: 0.12000; Price @ 1K: 0.16875; ProcessType: SMT; RoHS: Yes; Tolerance: 20%; Vendor: DIGIKEY; Vendor Part#: 587-1958-1-ND; Vendor_Part_No: 587-1958-1-ND; Voltage: 10V; eI Part#: 03_00263_01
FB13 = NFM_3: FILTER LC HIGH FREQ .47UF 0805; Distributor_name: DIGIKEY; Distributor_part_number: 490-2537-1-ND; EIC Part#: 04_00213_01; Manufacture: Murata; Manufacture Part Number: NFM21PC474R1C3D; Manufacture(English): Murata; Manufacture_Part_Number: NFM21PC474R1C3D; Manufacturer: Murata; Manufacturer_Part_No: NFM21PC474R1C3D; Mfg Part#: 04_00213_01; Mfr_name: Murata; Mfr_part_number: NFM21PC474R1C3D; Part #: 102569-1470R; RoHS: Yes; Tolerance: 20%; Vendor: DIGIKEY; Vendor Part#: 490-2537-1-ND; Vendor_Part_No: 490-2537-1-ND; eI Part#: 04_00213_01
R539 = 10_R_0: RES 0.0 OHM 1/10W JUMP 0402 SMD; Alt Mfg: Yageo; Distributor_name: DIGIKEY; Distributor_part_number: P0.0JCT-ND; EIC Part#: 02_00019_01; Manufacture: Panasonic - ECG; Manufacture Part Number: ERJ-2GE0R00X; Manufacture(English): Panasonic - ECG; Manufacture_Part_Number: ERJ-2GE0R00X; Manufacturer: Panasonic - ECG; Manufacturer_Part_No: ERJ-2GE0R00X; Mfg Part#: 02_00019_01; Mfr_name: Panasonic - ECG; Mfr_part_number: ERJ-2GE0R00X; Oper. Temp. Range: -55C to 125C; Package: 0402; ProcessType: SMT; Remark: Alt part is 1/16W; RoHS: Yes; Tolerance: 5%; Vendor: DIGIKEY; Vendor Part#: P0.0JCT-ND; Vendor_Part_No: P0.0JCT-ND; eI Part#: 02_00019_01
R554 = 10_R_0: RES 0.0 OHM 1/10W JUMP 0402 SMD; Alt Mfg: Yageo; Distributor_name: DIGIKEY; Distributor_part_number: P0.0JCT-ND; EIC Part#: 02_00019_01; Manufacture: Panasonic - ECG; Manufacture Part Number: ERJ-2GE0R00X; Manufacture(English): Panasonic - ECG; Manufacture_Part_Number: ERJ-2GE0R00X; Manufacturer: Panasonic - ECG; Manufacturer_Part_No: ERJ-2GE0R00X; Mfg Part#: 02_00019_01; Mfr_name: Panasonic - ECG; Mfr_part_number: ERJ-2GE0R00X; Mounting: NU; Mounting Status: NU; Mounting_status: NU; Oper. Temp. Range: -55C to 125C; Package: 0402; ProcessType: SMT; Remark: Alt part is 1/16W; RoHS: Yes; Tolerance: 5%; Vendor: DIGIKEY; Vendor Part#: P0.0JCT-ND; Vendor_Part_No: P0.0JCT-ND; eI Part#: 02_00019_01
TP14 = 00_TP-S40_0: TEST PAD TP; Distributor_name: NA; Distributor_part_number: NA; EIC Part#: NA; Manufacture: NA; Manufacture Part Number: NA; Manufacture(English): NA; Manufacture_Part_Number: NA; Manufacturer: NA; Manufacturer_Part_No: NA; Mfg: NA; Mfg Part#: NA; Mfr_name: NA; Mfr_part_number: NA; Oper. Temp. Range: --NA--; Package: --NA--; Price @ 1: NA; Price @ 10K: NA; Price @ 1K: NA; ProcessType: SMT; RoHS: Yes; Vendor: NA; Vendor Part#: --NA--; Vendor_Part_No: NA; eI Part#: NA

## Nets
GND: C14.1 C59.2 C64.2 C70.2 C71.1 C72.1 C73.1 C401.2 C403.2 C410.2 C415.2 C416.2 C417.2 C418.2 C419.2 C425.2 C426.2 C428.2 C432.2 C433.2 C435.2 C436.2 C438.2 C439.2 C442.2 C443.2 C444.2 C445.2 C446.2 C448.2 C449.2 C452.2 C453.2 C454.2 C457.2 C458.2 C459.2 C465.2 C466.2 C467.2 C470.2 C471.2 C757.2 C772.1 C773.2 C788.2 C790.2 C894.1 C940.1 CN1.2(GND_1) CN1.3(GND_2) CN1.4(GND_3) CN1.5(GND_4) CN6.3 FB13.2 FB13.4 GPS1.A1(GPS_GND_1) GPS1.A2(GPS_GND_2) GPS1.B2(GPS_GND_3) GPS1.E2(GND_1) GPS1.E6(GND_4) GPS1.F2(GND_2) GPS1.F5(GND_3) OSC1.2(GND) R71.2 R539.1 R660.1 SIM1.C5 SIM1.H1(SMDFIX2) SIM1.H2(SMDFIX1) U7.A19(VSS.1) U7.H1(SATA_VSS.1) U7.H2(SATA_VSS.2) U7.H8(VSS.2) U7.H9(VSS.3) U7.H15(VSS.4) U7.J7(VSS.5) U7.J8(VSS.6) U7.J9(VSS.7) U7.J10(VSS.8) U7.J11(VSS.9) U7.K1(SATA_VSS.3) U7.K2(SATA_VSS.4) U7.K7(VSS.10) U7.K8(VSS.11) U7.K9(VSS.12) U7.K10(VSS.13) U7.K11(VSS.14) U7.L3(SATA_VSS.5) U7.L5(VSS.15) U7.L7(VSS.16) U7.L8(VSS.17) U7.L9(VSS.18) U7.L10(VSS.19) U7.L11(VSS.20) U7.M1(SATA_VSS.6) U7.M4(VSS.21) U7.M5(VSS.22) U7.M6(VSS.23) U7.M7(VSS.24) U7.M10(VSS.25) U7.M11(VSS.26) U7.N5(VSS.27) U7.N11(VSS.28) U7.N12(VSS.29) U7.P11(VSS.30) U67.10(GND) U67.17(EPAD) U74.4(GND) U74.7(~{G}) U75.11(GND) U76.2(GND) ; also on sheet 1 2 3 4 5 6 8 10 11 12 13 14 15 16 17 18 19 20 21 25 26 27 28 29 33 34 35 36 37 40 41 42 43 45 46 47
VCC1V8: C14.2 C70.1 C71.2 C73.2 C772.2 C894.2 CN6.1 GPS1.F1(VDD_IO) OSC1.1(OE) OSC1.4(VCC) R96.1 R665.1 R689.2 R775.1 U67.3(VCC) U74.8(VCC) U75.2(VCCA) U76.5(VCC) ; also on sheet 2 6 8 11 19 21 25 26 27 29 33 34 36 37 41
VCC3V3_AUX: C773.1 L5.2 U67.5(VBATT) ; also on sheet 2 4 6 8 11 12 13 16 18 19 25 26 27 28 29 33 35 37 40 45 47
VCC3V3_MP: C940.2 U75.19(VCCB) ; also on sheet 4 5 18 37 41
BMC_GPIOINT0_FPGA_1V8_EXP2: U75.1(A1) ; also on sheet 28
BMC_GPIOINT0_FPGA_1V8_EXP2_T: U75.20(B1) ; also on sheet 5
BMC_GPIOINT1_FPGA_1V8_EXP3: U75.3(A2) ; also on sheet 28
BMC_GPIOINT1_FPGA_1V8_EXP3_T: U75.18(B2) ; also on sheet 5
BMC_GPIOINT2_FPGA_1V8_EXP1: U75.4(A3) ; also on sheet 28
BMC_GPIOINT2_FPGA_1V8_EXP1_T: U75.17(B3) ; also on sheet 5
BMC_GPS_EN_FPGA_1V8_EXP3: R70.1 ; also on sheet 28
BMC_TRGRSTZ: U75.16(B4) ; also on sheet 5
DDR_DVDD18: R554.2 U7.N6(DDR_DVDD18.1) U7.N9(DDR_DVDD18.2) U7.N10(DDR_DVDD18.3) U7.P7(DDR_DVDD18.4) U7.P8(DDR_DVDD18.5) U7.P9(DDR_DVDD18.6) U7.P10(DDR_DVDD18.7) U7.R7(DDR_DVDD18.8) U7.R8(DDR_DVDD18.9) U7.R9(DDR_DVDD18.10)
EXP_UART1_RXD_3V3: U75.12(B8) ; also on sheet 26
EXP_UART1_TXD_3V3: U75.15(B5) ; also on sheet 26
EXP_UARTTXD: U75.9(A8) U76.6(Y0)
GPS_ENABLE: GPS1.C4(GPS_ENABLE) R70.2 R71.1
GPS_PPS: GPS1.C1(GPS_PPS) ; also on sheet 26
GPS_RF: C59.1 GPS1.B1(GPS_RF) L4.2
GPS_RTC_CLK: GPS1.C5(RTC_CLK) R44.1
GPS_RTC_CLK_R: OSC1.3(OUT) R44.2
GPS_UARTRXD: R76.1 U74.2(B)
GPS_UARTRXD_R: GPS1.C3(GPS_TX) R76.2
GPS_UARTTXD: GPS1.B3(GPS_RX) U76.4(Y1)
PLL0_VDDA12: C401.1 C403.1 FB13.3 U7.L15(PLL0_VDDA12) U7.N15(PLL1_VDDA12)
SIM_CLK: SIM1.C3 U67.11(SIM_CLK)
SIM_EN: C757.1 R660.2 SIM1.SW2 U67.1(EN)
SIM_IO: R694.1 SIM1.C7 U67.8(SIM_I/O)
SIM_RST: SIM1.C2 U67.9(SIM_RST)
SIM_SEL: CN6.2 U67.2(SEL)
SIM_VCC: C788.1 C790.1 R694.2 SIM1.C1 U67.7(VSIM)
SOC_GPIO_8_FPGA_1V8_EXP2: U74.6(~{A}/B) ; also on sheet 16 21 28
SOC_GPIO_11_FPGA_1V8_EXP2: U76.1(A) ; also on sheet 16 21 28
SOC_SIM_CLK: U67.13(CLK) ; also on sheet 29
SOC_SIM_IO: R689.1 U67.15(I/O) ; also on sheet 29
SOC_SIM_RST: U67.14(RST) ; also on sheet 29
SOC_UART1_RXD_1V8: U74.1(A) U75.6(A5)
SOC_UART1_TXD_1V8: U76.3(~{E}) ; also on sheet 29
TRGRSTZ: U75.5(A4) ; also on sheet 6 42
UART1_RXD_M: U74.5(Y) ; also on sheet 29
XDS_1V2: C410.1 C415.1 C418.1 C425.1 C436.1 C438.1 C442.1 C444.1 C445.1 C448.1 C449.1 C453.1 C466.1 C470.1 FB13.1 U7.E5(RVDD.1) U7.E15(CVDD.1) U7.G7(CVDD.2) U7.G8(CVDD.3) U7.G13(CVDD.4) U7.H6(CVDD.5) U7.H7(CVDD.6) U7.H10(CVDD.7) U7.H11(CVDD.8) U7.H12(CVDD.9) U7.H13(CVDD.10) U7.H14(RVDD.2) U7.J6(CVDD.11) U7.J12(CVDD.12) U7.K6(CVDD.13) U7.K12(CVDD.14) U7.L12(CVDD.15) U7.L14(RTC_CVDD) U7.M8(CVDD.16) U7.M9(CVDD.17) U7.M12(USB_CVDD) U7.N7(RVDD.3) U7.N8(CVDD.18) ; also on sheet 15
XDS_1V8: C419.1 C432.1 C433.1 C443.1 C452.1 C458.1 R554.1 U7.F14(DVDD18.1) U7.G6(DVDD18.2) U7.G10(DVDD18.3) U7.G11(DVDD18.4) U7.G12(DVDD18.5) U7.J13(DVDD18.6) U7.K5(DVDD18.7) U7.L6(DVDD18.8) U7.P13(DVDD18.9) U7.R13(DVDD18.10) ; also on sheet 10 15 42
XDS_VCC3V3: C416.1 C417.1 C426.1 C428.1 C435.1 C439.1 C446.1 C454.1 C457.1 C459.1 C465.1 C467.1 C471.1 U7.E14(DVDD3318_B.1) U7.F5(DVDD3318_A.1) U7.F6(DVDD3318_B.2) U7.F7(DVDD3318_B.3) U7.F8(DVDD3318_B.4) U7.F10(DVDD3318_B.5) U7.F11(DVDD3318_B.6) U7.F12(DVDD3318_B.7) U7.F13(DVDD3318_B.8) U7.F15(DVDD3318_A.4) U7.G5(DVDD3318_A.2) U7.G9(DVDD3318_B.9) U7.G14(DVDD3318_A.5) U7.G15(DVDD3318_A.6) U7.H5(DVDD3318_A.3) U7.J5(DVDD3318_C.1) U7.J14(DVDD3318_B.10) U7.K13(DVDD3318_C.2) U7.K15(DVDD3318_B.11) U7.L4(DVDD3318_C.3) U7.L13(DVDD3318_C.4) U7.M13(DVDD3318_C.5) U7.N13(DVDD3318_C.6) U7.P5(DVDD3318_C.7) U7.P6(DVDD3318_C.8) U7.P12(DVDD3318_C.9) U7.R4(DVDD3318_C.10) ; also on sheet 10 14 15 42
N17739519: C72.2 GPS1.E1(VDD) R96.2
N17739827: GPS1.C2(TCXO_CLK) TP23.1
N17740166: R665.2 SIM1.SW1
N17740213: C57.2 C64.1 L4.1
N17740227: C57.1 CN1.1(RF_IN) L5.1
N17742431: R775.2 U75.10(OE)
N18205446: TP14.1 U7.T19(RSV2(VPP))
N18206324: R539.2 U7.M15(PLL1_VSSA12) U7.M17(PLL0_VSSA12)

Not connected (* = marked no-connect by the designer): GPS1 A3(NU_8)* A4(NU_9)* A5(NU_6)* A6(NU_7)* B4(NU_13)* B5(NU_14)* B6(NU_10)* C6(NU_11)* D1(NU_2)* D2(NU_3)* D3(NU_4)* D4(NU_5)* D5(NU_19)* D6(NU_12)* E3(NU_18)* E4(NU_15)* E5(NU_17)* F3(NU_16)* F4(NU_20)* F6(NU_1)*; SIM1 C6*; U7 J1(SATA_TXP)* J2(SATA_TXN)* L1(SATA_RXP)* L2(SATA_RXN)* M2(SATA_VDD.1)* M3(NC.M3)* N1(SATA_REFCLKN)* N2(SATA_REFCLKP)* N3(SATA_REG)* N4(SATA_VDD.2)* P1(SATA_VDD.3)* P2(SATA_VDD.4)* P3(SATA_VDDR)*; U67 4(NC1)* 6(NC2)* 12(NC3)* 16(NC4)*; U74 3(~{Y})*; U75 7(A6)* 8(A7)* 13(B7)* 14(B6)*

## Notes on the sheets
sheet 22
- USIM, SOC UART 1.8v switching, 1.8v/3.3v GPIO INT, SOC UART, GPS
- USIM
- GPS
- High
- Low (Default)
- SIM_SEL
- VCC_SIM Value = 2.95V
- VCC_SIM Value = 1.8V
- SOC UART 1.8v switching
- FOR ANTENNA CIRCUIT
- Note:GPIO8
  0, SOC_UART0_Rxd -> UART1_Rxd
  1, GPS_UARTRxd -> UART1_Rxd
- Note:GPIO11
  0, SOC_UART1 -> EXP_UARTTX0
  1, SOC_UART1 -> GPS_UARTTX0
- SPI level shift  3.3V <=> 1.8V
sheet 24
- XDS200 Power
- NOT USED
- DDR PHY DOES NOT
  REQUIRE POWER IF NOT
  USED, PER DATA SHEET,
  BUT NOT A TYPICAL USE
  CASE.
- NOT USED
